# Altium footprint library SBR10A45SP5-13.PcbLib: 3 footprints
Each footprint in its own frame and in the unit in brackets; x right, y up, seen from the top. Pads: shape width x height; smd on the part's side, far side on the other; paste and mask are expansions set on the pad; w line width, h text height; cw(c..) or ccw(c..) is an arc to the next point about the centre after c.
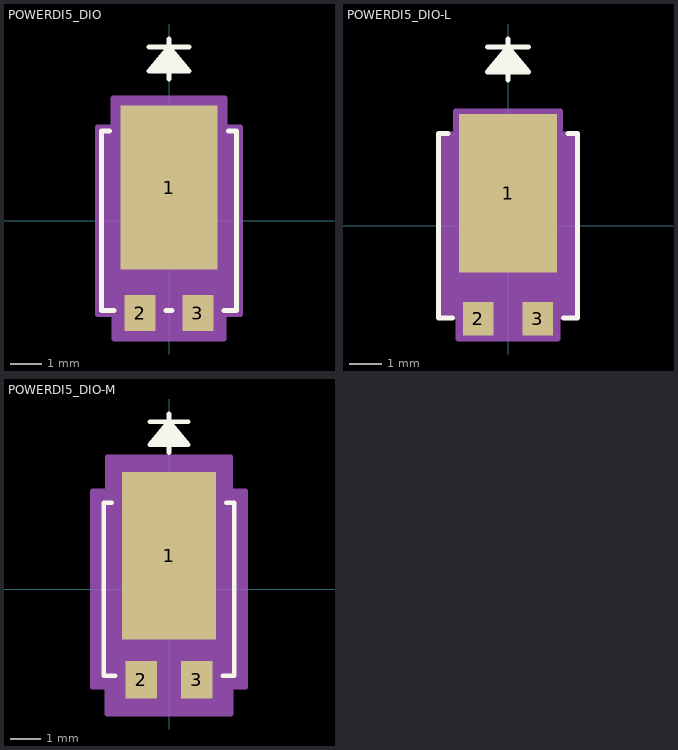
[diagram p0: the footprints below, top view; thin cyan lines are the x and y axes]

## POWERDI5_DIO [mil]
pads (3):
  rect 122x205 smd paste+0 mask+0: 1(0,41.5)
  rect 39x45 smd paste+0 mask+0: 2(-36.22,-115.5) 3(36.22,-115.5)
Top Overlay:
  lines w6: -74.1,112.5 -84.5,112.5 -84.5,-112.5 -68.82,-112.5 ; -25,217.5 25,217.5 ; -20,187.5 0,217.5 ; -15,187.5 0,217.5 ; -10,187.5 0,217.5 ; -5,187.5 0,217.5 ; -3.62,-112.5 3.62,-112.5 ; 0,177.5 0,227.5 ; 5,187.5 0,217.5 ; 10,187.5 0,217.5 ; 15,187.5 0,217.5 ; 20,187.5 0,217.5 ; 68.82,-112.5 84.5,-112.5 84.5,112.5 74.1,112.5 ; 0,217.5 25,187.5 -25,187.5 0,217.5
  text ".Designator" at -137.5,-25 h50
Mechanical 13:
  lines w1: -25,217.5 25,217.5 ; -20,187.5 0,217.5 ; -15,187.5 0,217.5 ; -10,187.5 0,217.5 ; -5,187.5 0,217.5 ; 0,177.5 0,227.5 ; 5,187.5 0,217.5 ; 10,187.5 0,217.5 ; 15,187.5 0,217.5 ; 20,187.5 0,217.5 ; 0,217.5 25,187.5 -25,187.5 0,217.5 ; -79.5,-107.5 79.5,-107.5 79.5,107.5 -79.5,107.5 -79.5,-107.5
  text ".Designator" at -137.5,-25 h50
Mechanical 15:
  region: -68.72,-117.5 -89.5,-117.5 -89.5,117.5 -70,117.5 -70,154 70,154 70,117.5 89.5,117.5 89.5,-117.5 68.72,-117.5 68.72,-148 -68.72,-148
  region: 79.5,-107.5 -79.5,-107.5 -79.5,107.5 79.5,107.5
  lines w6: -89.5,-117.5 -89.5,117.5 -70,117.5 -70,154 70,154 70,117.5 89.5,117.5 89.5,-117.5 68.72,-117.5 68.72,-148 -68.72,-148 -68.72,-117.5 -89.5,-117.5
3D body "POWERDI5_DIO.step": height 47.09, standoff 0, extent -79.49,-130 79.49,130

## POWERDI5_DIO-L [mil]
pads (3):
  rect 120x193 smd paste+0 mask+0: 1(0,39.5)
  rect 37x41 smd paste+0 mask+0: 2(-36.22,-113.5) 3(36.22,-113.5)
Top Overlay:
  lines w6: -73.1,112.5 -84.5,112.5 -84.5,-112.5 -67.82,-112.5 ; -25,217.5 25,217.5 ; -20,187.5 0,217.5 ; -15,187.5 0,217.5 ; -10,187.5 0,217.5 ; -5,187.5 0,217.5 ; 0,177.5 0,227.5 ; 5,187.5 0,217.5 ; 10,187.5 0,217.5 ; 15,187.5 0,217.5 ; 20,187.5 0,217.5 ; 67.82,-112.5 84.5,-112.5 84.5,112.5 73.1,112.5 ; 0,217.5 25,187.5 -25,187.5 0,217.5
  text ".Designator" at -137.5,-25 h50
Mechanical 13:
  lines w1: -25,217.5 25,217.5 ; -20,187.5 0,217.5 ; -15,187.5 0,217.5 ; -10,187.5 0,217.5 ; -5,187.5 0,217.5 ; 0,177.5 0,227.5 ; 5,187.5 0,217.5 ; 10,187.5 0,217.5 ; 15,187.5 0,217.5 ; 20,187.5 0,217.5 ; 0,217.5 25,187.5 -25,187.5 0,217.5 ; -79.5,-107.5 79.5,-107.5 79.5,107.5 -79.5,107.5 -79.5,-107.5
  text ".Designator" at -137.5,-25 h50
Mechanical 15:
  region: -60.72,-111.5 -83.5,-111.5 -83.5,111.5 -64,111.5 -64,140 64,140 64,111.5 83.5,111.5 83.5,-111.5 60.72,-111.5 60.72,-138 -60.72,-138
  region: 79.5,-107.5 -79.5,-107.5 -79.5,107.5 79.5,107.5
  lines w6: -83.5,-111.5 -83.5,111.5 -64,111.5 -64,140 64,140 64,111.5 83.5,111.5 83.5,-111.5 60.72,-111.5 60.72,-138 -60.72,-138 -60.72,-111.5 -83.5,-111.5
3D body "POWERDI5_DIO.step": height 47.09, standoff 0, extent -79.49,-130 79.49,130

## POWERDI5_DIO-M [mil]
pads (3):
  rect 122x217 smd paste+0 mask+0: 1(0,43.5)
  rect 41x49 smd paste+0 mask+0: 2(-36.22,-117.5) 3(36.22,-117.5)
Top Overlay:
  lines w6: -74.1,112.5 -84.5,112.5 -84.5,-112.5 -69.82,-112.5 ; -25,217.5 25,217.5 ; -20,187.5 0,217.5 ; -15,187.5 0,217.5 ; -10,187.5 0,217.5 ; -5,187.5 0,217.5 ; 0,177.5 0,227.5 ; 5,187.5 0,217.5 ; 10,187.5 0,217.5 ; 15,187.5 0,217.5 ; 20,187.5 0,217.5 ; 69.82,-112.5 84.5,-112.5 84.5,112.5 74.1,112.5 ; 0,217.5 25,187.5 -25,187.5 0,217.5
  text ".Designator" at -137.5,-25 h50
Mechanical 13:
  lines w1: -25,217.5 25,217.5 ; -20,187.5 0,217.5 ; -15,187.5 0,217.5 ; -10,187.5 0,217.5 ; -5,187.5 0,217.5 ; 0,177.5 0,227.5 ; 5,187.5 0,217.5 ; 10,187.5 0,217.5 ; 15,187.5 0,217.5 ; 20,187.5 0,217.5 ; 0,217.5 25,187.5 -25,187.5 0,217.5 ; -79.5,-107.5 79.5,-107.5 79.5,107.5 -79.5,107.5 -79.5,-107.5
  text ".Designator" at -137.5,-25 h50
Mechanical 15:
  region: -80.72,-127.5 -99.5,-127.5 -99.5,127.5 -80,127.5 -80,172 80,172 80,127.5 99.5,127.5 99.5,-127.5 80.72,-127.5 80.72,-162 -80.72,-162
  region: 79.5,-107.5 -79.5,-107.5 -79.5,107.5 79.5,107.5
  lines w6: -99.5,-127.5 -99.5,127.5 -80,127.5 -80,172 80,172 80,127.5 99.5,127.5 99.5,-127.5 80.72,-127.5 80.72,-162 -80.72,-162 -80.72,-127.5 -99.5,-127.5
3D body "POWERDI5_DIO.step": height 47.09, standoff 0, extent -79.49,-130 79.49,130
